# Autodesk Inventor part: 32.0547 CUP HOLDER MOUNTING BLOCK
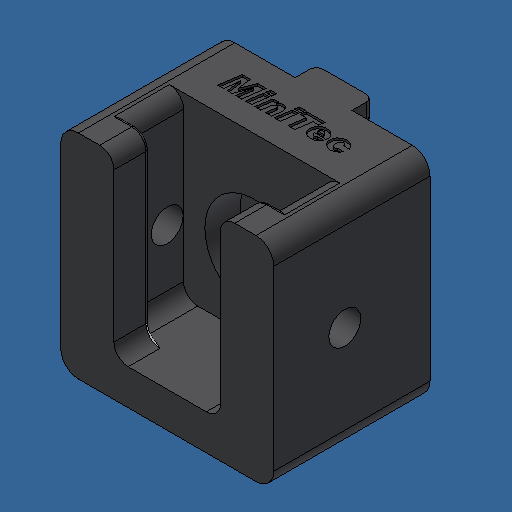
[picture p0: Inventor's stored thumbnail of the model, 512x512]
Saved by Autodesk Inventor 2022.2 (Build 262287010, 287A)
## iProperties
Created: 2014-10
Part Number: 32.0547 CUP HOLDER MOUNTING BLOCK
Material: ABS Plastic
Document SubType Name: Modeling
Designer: Admin
Density: 1.06 g/cm^3
Mass: 11.8053 g
Surface Area: 65.6348 cm^2
Volume: 11.137 cm^3
Appearance: Bubblegum
Author: Admin
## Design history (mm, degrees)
feature "Base1"
body "Solid1"
